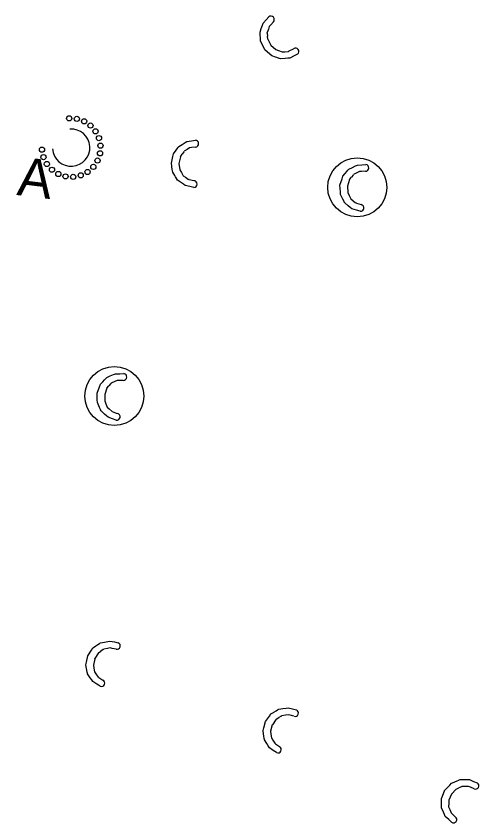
# Model space of a CAD drawing. Extents: x 2470000 to 2520000, y 340000 to 380000.
# Drawn here: x 2482994.8 to 2483175.1, y 365771.5 to 366085.9 of the extents above; entities that cross this region are included whole.
import ezdxf

# ---------------------------------------------------------------- set-up
doc = ezdxf.new("R2010")
doc.units = 0
for name, color, linetype in [('Coir Fiber Wattle with PAM Both CELL', 7, 'Continuous'), ('Label A Final CELL', 7, 'Continuous'), ('Rock Pipe Inlet Sediment Trap Type A Final CELL', 7, 'Continuous'), ('Wattle Both CELL', 7, 'Continuous'), ('Wattle Final CELL', 7, 'Continuous')]:
    doc.layers.add(name, color=color, linetype=linetype)

# ---------------------------------------------------------------- blocks, each defined once
blk = doc.blocks.new('A3')
at = {"layer": 'Label A Final CELL'}
blk.add_text('A', height=0.3, dxfattribs=at).set_placement((-0.133, -0.151))

msp = doc.modelspace()

# ---------------------------------------------------------------- linework, layer by layer
at = {"layer": 'Coir Fiber Wattle with PAM Both CELL'}
for p, q in [((2483126.17, 366023.96), (2483125.47, 366023.09)), ((2483126.17, 366023.96), (2483126.31, 366024.14)), ((2483127.61, 366024.79), (2483126.31, 366024.14)), ((2483128.6, 366025.28), (2483127.61, 366024.79)), ((2483129.39, 366025.32), (2483128.6, 366025.28)), ((2483130.94, 366025.41), (2483129.39, 366025.32)), ((2483124.72, 366022.17), (2483123.95, 366019.65)), ((2483124.72, 366022.17), (2483125.47, 366023.09)), ((2483123.95, 366019.64), (2483123.95, 366019.65)), ((2483123.95, 366019.64), (2483124.06, 366017.1)), ((2483124.06, 366017.1), (2483124.57, 366016.01)), ((2483124.57, 366016.01), (2483125.18, 366014.7)), ((2483125.18, 366014.7), (2483125.97, 366014.04)), ((2483125.97, 366014.04), (2483127.1, 366013.09)), ((2483127.42, 366012.99), (2483127.1, 366013.09)), ((2483127.42, 366012.99), (2483129.19, 366012.42)), ((2483030.22, 365940.97), (2483031.01, 365941.87)), ((2483031.74, 365942.7), (2483031.01, 365941.87)), ((2483031.74, 365942.7), (2483031.9, 365942.88)), ((2483033.23, 365943.47), (2483031.9, 365942.88)), ((2483034.24, 365943.91), (2483033.23, 365943.47)), ((2483035.03, 365943.93), (2483034.24, 365943.91)), ((2483036.58, 365943.94), (2483035.03, 365943.93)), ((2483030.22, 365940.97), (2483029.34, 365938.49)), ((2483029.34, 365938.48), (2483029.34, 365938.49)), ((2483029.34, 365938.48), (2483029.34, 365935.94)), ((2483029.34, 365935.94), (2483029.8, 365934.83)), ((2483029.8, 365934.83), (2483030.35, 365933.49)), ((2483030.35, 365933.49), (2483031.11, 365932.8)), ((2483031.11, 365932.8), (2483032.21, 365931.8)), ((2483032.52, 365931.69), (2483032.21, 365931.8)), ((2483032.52, 365931.69), (2483034.26, 365931.04))]:
    msp.add_line(p, q, dxfattribs=at)
for points in [[(2483128.88, 366009.85), (2483127.39, 366010.3), (2483125.65, 366010.83), (2483125, 366011.36), (2483124.22, 366012), (2483122.84, 366013.15), (2483122.82, 366013.18), (2483122.63, 366013.58), (2483122.59, 366013.65), (2483122.17, 366014.5), (2483121.88, 366015.1), (2483121.23, 366016.42), (2483121.16, 366017.46), (2483121, 366020), (2483121, 366020.01), (2483121.81, 366022.52), (2483122.12, 366023.5), (2483122.86, 366024.36), (2483123.01, 366024.55), (2483123.63, 366025.28), (2483124.11, 366025.83), (2483124.22, 366025.96), (2483124.46, 366026.24), (2483124.47, 366026.24), (2483125.83, 366026.9), (2483127.03, 366027.49), (2483127.76, 366027.84), (2483129.52, 366027.96), (2483131.06, 366028.07)], [(2483033.83, 365928.48), (2483032.36, 365929), (2483030.65, 365929.61), (2483030.03, 365930.16), (2483029.28, 365930.84), (2483027.95, 365932.05), (2483027.93, 365932.08), (2483027.75, 365932.49), (2483027.72, 365932.56), (2483027.34, 365933.43), (2483027.07, 365934.04), (2483026.49, 365935.38), (2483026.46, 365936.43), (2483026.41, 365938.97), (2483026.41, 365938.99), (2483027.33, 365941.46), (2483027.68, 365942.43), (2483028.46, 365943.25), (2483028.62, 365943.43), (2483029.27, 365944.13), (2483029.77, 365944.66), (2483029.89, 365944.79), (2483030.14, 365945.06), (2483030.15, 365945.06), (2483031.53, 365945.66), (2483032.77, 365946.19), (2483033.51, 365946.51), (2483035.27, 365946.55), (2483036.82, 365946.59)]]:
    msp.add_lwpolyline(points, dxfattribs=at)
for centre in [(2483127.72, 366019.16), (2483033.08, 365937.84)]:
    msp.add_circle(centre, 11.5, dxfattribs=at)
for centre, radius, start, end in [((2483130.9, 366026.74), 1.33, 271.8897, 83.0023), ((2483129.04, 366011.13), 1.3, 263.0023, 83.0023), ((2483036.6, 365945.28), 1.33, 269.3732, 80.4859), ((2483034.05, 365929.76), 1.3, 260.4859, 80.4859)]:
    msp.add_arc(centre, radius, start, end, dxfattribs=at)
at = {"layer": 'Rock Pipe Inlet Sediment Trap Type A Final CELL'}
for centre in [(2483015.52, 366046.03), (2483018.5, 366045.84), (2483021.33, 366044.89), (2483023.81, 366043.24), (2483025.78, 366041), (2483027.11, 366038.33), (2483027.7, 366035.41), (2483004.91, 366033.85), (2483027.52, 366032.43), (2483005.5, 366030.92), (2483026.57, 366029.61), (2483006.82, 366028.25), (2483008.8, 366026.02), (2483024.92, 366027.12), (2483011.28, 366024.37), (2483014.11, 366023.42), (2483017.09, 366023.23), (2483020.01, 366023.82), (2483022.68, 366025.15)]:
    msp.add_circle(centre, 1.01, dxfattribs=at)
msp.add_arc((2483016.3, 366034.63), 7.26, 183.9246, 93.9157, dxfattribs=at)
at = {"layer": 'Wattle Both CELL'}
for p, q in [((2483060.13, 366032.99), (2483059.5, 366032.07)), ((2483060.13, 366032.99), (2483060.26, 366033.19)), ((2483061.5, 366033.94), (2483060.26, 366033.19)), ((2483062.44, 366034.52), (2483061.5, 366033.94)), ((2483063.22, 366034.63), (2483062.44, 366034.52)), ((2483064.76, 366034.84), (2483063.22, 366034.63)), ((2483058.84, 366031.09), (2483058.28, 366028.51)), ((2483058.84, 366031.09), (2483059.5, 366032.07)), ((2483058.28, 366028.5), (2483058.28, 366028.51)), ((2483058.28, 366028.5), (2483058.61, 366025.98)), ((2483058.61, 366025.98), (2483059.21, 366024.94)), ((2483059.21, 366024.94), (2483059.93, 366023.68)), ((2483059.93, 366023.68), (2483060.77, 366023.09)), ((2483060.77, 366023.09), (2483061.98, 366022.25)), ((2483062.31, 366022.17), (2483061.98, 366022.25)), ((2483062.31, 366022.17), (2483064.12, 366021.76)), ((2483026.92, 365837.73), (2483027.89, 365838.42)), ((2483028.79, 365839.07), (2483027.89, 365838.42)), ((2483028.79, 365839.07), (2483028.99, 365839.2)), ((2483030.41, 365839.48), (2483028.99, 365839.2)), ((2483031.49, 365839.69), (2483030.41, 365839.48)), ((2483032.27, 365839.52), (2483031.49, 365839.69)), ((2483033.78, 365839.19), (2483032.27, 365839.52)), ((2483025.5, 365835.5), (2483024.93, 365833.03)), ((2483026.92, 365837.73), (2483025.5, 365835.52)), ((2483025.5, 365835.5), (2483025.5, 365835.52)), ((2483024.93, 365833.03), (2483025.12, 365831.84)), ((2483025.12, 365831.84), (2483025.36, 365830.41)), ((2483025.36, 365830.41), (2483025.94, 365829.57)), ((2483025.94, 365829.57), (2483026.78, 365828.35)), ((2483027.06, 365828.17), (2483026.78, 365828.35)), ((2483027.06, 365828.17), (2483028.61, 365827.14)), ((2483098.09, 365813.16), (2483097.16, 365812.55)), ((2483098.09, 365813.16), (2483098.29, 365813.29)), ((2483099.73, 365813.5), (2483098.29, 365813.29)), ((2483100.82, 365813.66), (2483099.73, 365813.5)), ((2483101.58, 365813.46), (2483100.82, 365813.66)), ((2483103.08, 365813.05), (2483101.58, 365813.46)), ((2483094.64, 365809.74), (2483093.96, 365807.29)), ((2483094.64, 365809.74), (2483094.65, 365809.75)), ((2483096.16, 365811.9), (2483094.65, 365809.75)), ((2483096.16, 365811.9), (2483097.16, 365812.55)), ((2483093.96, 365807.29), (2483094.1, 365806.1)), ((2483094.1, 365806.1), (2483094.27, 365804.66)), ((2483094.27, 365804.66), (2483094.82, 365803.79)), ((2483094.82, 365803.79), (2483095.61, 365802.54)), ((2483095.88, 365802.34), (2483095.61, 365802.54)), ((2483095.88, 365802.34), (2483097.38, 365801.25)), ((2483166.2, 365784.64), (2483164.39, 365782.73)), ((2483166.2, 365784.64), (2483167.28, 365785.14)), ((2483168.29, 365785.61), (2483167.28, 365785.14)), ((2483168.29, 365785.61), (2483168.5, 365785.71)), ((2483169.95, 365785.72), (2483168.5, 365785.71)), ((2483171.05, 365785.72), (2483169.95, 365785.72)), ((2483171.78, 365785.41), (2483171.05, 365785.72)), ((2483173.21, 365784.8), (2483171.78, 365785.41)), ((2483164.39, 365782.72), (2483163.37, 365780.39)), ((2483164.39, 365782.72), (2483164.39, 365782.73)), ((2483163.34, 365779.19), (2483163.31, 365777.74)), ((2483163.37, 365780.39), (2483163.34, 365779.19)), ((2483163.31, 365777.74), (2483163.73, 365776.8)), ((2483163.73, 365776.8), (2483164.33, 365775.45)), ((2483164.57, 365775.22), (2483164.33, 365775.45)), ((2483164.57, 365775.22), (2483165.91, 365773.93))]:
    msp.add_line(p, q, dxfattribs=at)
for points in [[(2483064.02, 366019.16), (2483062.5, 366019.49), (2483060.72, 366019.87), (2483060.04, 366020.34), (2483059.2, 366020.92), (2483057.73, 366021.94), (2483057.71, 366021.97), (2483057.48, 366022.35), (2483057.44, 366022.42), (2483056.95, 366023.24), (2483056.61, 366023.81), (2483055.85, 366025.06), (2483055.69, 366026.09), (2483055.31, 366028.61), (2483055.31, 366028.62), (2483055.9, 366031.2), (2483056.13, 366032.2), (2483056.79, 366033.12), (2483056.93, 366033.31), (2483057.49, 366034.09), (2483057.92, 366034.69), (2483058.02, 366034.82), (2483058.23, 366035.12), (2483058.24, 366035.13), (2483059.54, 366035.9), (2483060.69, 366036.58), (2483061.39, 366036.99), (2483063.13, 366037.27), (2483064.66, 366037.5)], [(2483027.62, 365824.75), (2483026.3, 365825.58), (2483024.77, 365826.56), (2483024.29, 365827.24), (2483023.71, 365828.07), (2483022.69, 365829.55), (2483022.68, 365829.59), (2483022.6, 365830.02), (2483022.58, 365830.09), (2483022.41, 365831.04), (2483022.29, 365831.69), (2483022.02, 365833.13), (2483022.23, 365834.15), (2483022.75, 365836.65), (2483022.76, 365836.66), (2483024.21, 365838.86), (2483024.78, 365839.72), (2483025.71, 365840.35), (2483025.91, 365840.48), (2483026.71, 365841.02), (2483027.32, 365841.43), (2483027.46, 365841.52), (2483027.76, 365841.73), (2483027.77, 365841.73), (2483029.26, 365842), (2483030.58, 365842.24), (2483031.38, 365842.38), (2483033.1, 365842.03), (2483034.61, 365841.71)], [(2483096.28, 365798.9), (2483095.01, 365799.8), (2483093.52, 365800.84), (2483093.07, 365801.54), (2483092.53, 365802.4), (2483091.57, 365803.92), (2483091.56, 365803.96), (2483091.5, 365804.39), (2483091.49, 365804.47), (2483091.36, 365805.42), (2483091.26, 365806.07), (2483091.06, 365807.53), (2483091.32, 365808.53), (2483091.95, 365811), (2483091.96, 365811.01), (2483093.5, 365813.15), (2483094.11, 365813.98), (2483095.07, 365814.57), (2483095.28, 365814.7), (2483096.1, 365815.2), (2483096.72, 365815.58), (2483096.87, 365815.67), (2483097.18, 365815.86), (2483097.19, 365815.86), (2483098.68, 365816.06), (2483100.01, 365816.24), (2483100.82, 365816.35), (2483102.52, 365815.92), (2483104.02, 365815.54)], [(2483164.48, 365771.75), (2483163.35, 365772.82), (2483162.02, 365774.06), (2483161.68, 365774.82), (2483161.26, 365775.75), (2483160.53, 365777.38), (2483160.53, 365777.42), (2483160.53, 365777.86), (2483160.52, 365777.94), (2483160.53, 365778.9), (2483160.53, 365779.56), (2483160.53, 365781.03), (2483160.93, 365781.99), (2483161.9, 365784.35), (2483161.91, 365784.36), (2483163.74, 365786.25), (2483164.46, 365786.99), (2483165.5, 365787.44), (2483165.71, 365787.53), (2483166.6, 365787.91), (2483167.27, 365788.2), (2483167.43, 365788.27), (2483167.76, 365788.41), (2483167.77, 365788.41), (2483169.28, 365788.4), (2483170.62, 365788.39), (2483171.43, 365788.39), (2483173.06, 365787.72), (2483174.49, 365787.14)]]:
    msp.add_lwpolyline(points, dxfattribs=at)
for centre, radius, start, end in [((2483064.61, 366036.17), 1.33, 276.7469, 87.8595), ((2483064.07, 366020.46), 1.3, 267.8595, 87.8595), ((2483034.1, 365840.48), 1.33, 256.3171, 67.4298), ((2483028.12, 365825.95), 1.3, 247.4298, 67.4298), ((2483103.46, 365814.33), 1.33, 253.7766, 64.8892), ((2483096.83, 365800.08), 1.3, 244.8892, 64.8892), ((2483173.76, 365786.02), 1.33, 245.6677, 56.7803), ((2483165.19, 365772.84), 1.3, 236.7803, 56.7803)]:
    msp.add_arc(centre, radius, start, end, dxfattribs=at)
at = {"layer": 'Wattle Final CELL'}
for p, q in [((2483095.05, 366083.61), (2483094, 366082.46)), ((2483093.11, 366080.83), (2483092.64, 366079.46)), ((2483093.47, 366081.87), (2483093.11, 366080.83)), ((2483094, 366082.46), (2483093.47, 366081.87)), ((2483092.66, 366079.23), (2483092.64, 366079.46)), ((2483092.66, 366079.23), (2483092.77, 366078.12)), ((2483092.89, 366076.93), (2483092.77, 366078.12)), ((2483092.89, 366076.93), (2483094.11, 366074.6)), ((2483094.11, 366074.59), (2483094.11, 366074.6)), ((2483094.11, 366074.59), (2483095.98, 366072.86)), ((2483095.98, 366072.86), (2483097.11, 366072.44)), ((2483097.11, 366072.44), (2483098.46, 366071.93)), ((2483098.46, 366071.93), (2483099.48, 366072.02)), ((2483099.48, 366072.02), (2483100.96, 366072.14)), ((2483101.26, 366072.29), (2483100.96, 366072.14)), ((2483101.26, 366072.29), (2483102.92, 366073.13))]:
    msp.add_line(p, q, dxfattribs=at)
msp.add_lwpolyline([(2483104.5, 366071.07), (2483103.12, 366070.35), (2483101.51, 366069.51), (2483100.68, 366069.43), (2483099.67, 366069.34), (2483097.88, 366069.19), (2483097.84, 366069.2), (2483097.43, 366069.35), (2483097.35, 366069.37), (2483096.45, 366069.69), (2483095.82, 366069.91), (2483094.44, 366070.39), (2483093.66, 366071.08), (2483091.76, 366072.78), (2483091.75, 366072.79), (2483090.56, 366075.14), (2483090.1, 366076.06), (2483090.02, 366077.19), (2483090, 366077.43), (2483089.94, 366078.39), (2483089.89, 366079.12), (2483089.88, 366079.29), (2483089.85, 366079.65), (2483089.85, 366079.66), (2483090.36, 366081.08), (2483090.81, 366082.35), (2483091.08, 366083.11), (2483092.24, 366084.43), (2483093.27, 366085.59)], dxfattribs=at)
for centre, radius, start in [((2483094.08, 366084.53), 1.33, 316.4492), ((2483103.71, 366072.1), 1.3, 307.5618)]:
    msp.add_arc(centre, radius, start, 127.5618, dxfattribs=at)

# ---------------------------------------------------------------- block references
at = {"layer": 'Rock Pipe Inlet Sediment Trap Type A Final CELL', "xscale": 50.00000000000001, "yscale": 49.99999999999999, "rotation": -6.997703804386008}
msp.add_blockref('A3', (2483002.33, 366022.89), dxfattribs=at)

doc.saveas('drawing.dxf')
